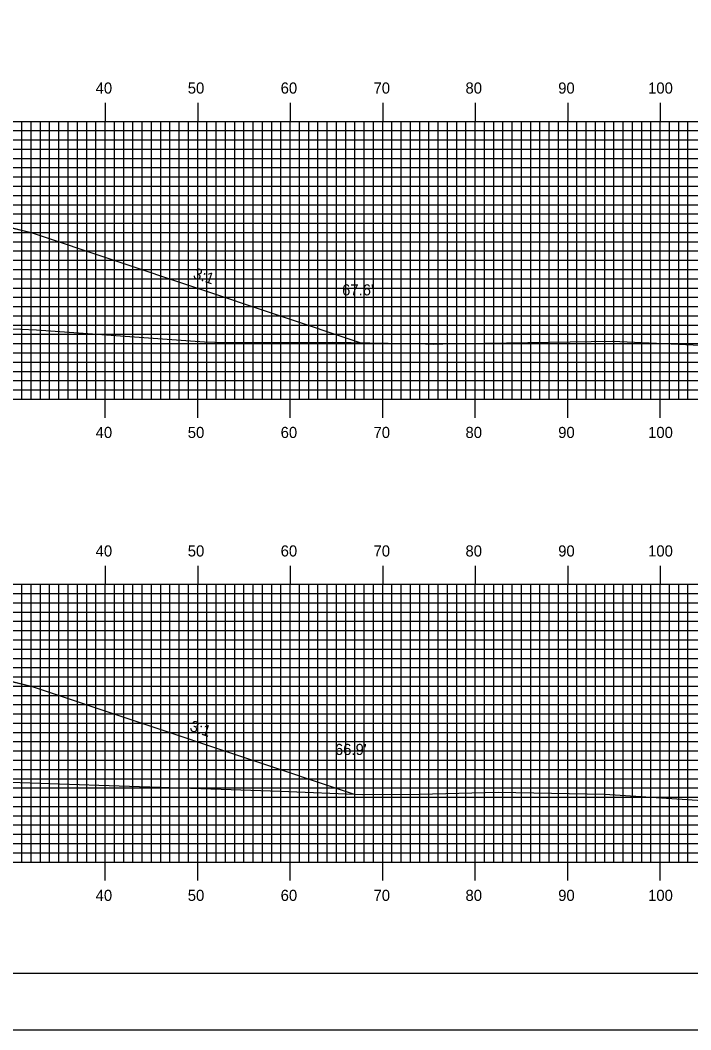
# Model space of a CAD drawing. Extents: x 1806258 to 1806601, y 442591 to 442811.
# Drawn here: x 1806454.5 to 1806527, y 442590.5 to 442699.6 of the extents above; entities that cross this region are included whole.
import ezdxf

# ---------------------------------------------------------------- set-up
doc = ezdxf.new("R2010")
doc.units = 0
for name, color, linetype in [('ANNOTATION', 7, 'Continuous'), ('BORDER', 7, 'Continuous'), ('D_Roadway_Centerline', 7, 'Continuous'), ('D_Roadway_SlopeLines', 7, 'Continuous'), ('D_Text_Standard', 7, 'Continuous'), ('H_V ANNOTATION', 7, 'Continuous'), ('MAJOR', 7, 'Continuous'), ('MINOR', 7, 'Continuous'), ('PLOT BOUNDARY', 7, 'Continuous'), ('S_Roadway_Centerline', 7, 'Continuous')]:
    doc.layers.add(name, color=color, linetype=linetype)

msp = doc.modelspace()

# ---------------------------------------------------------------- linework, layer by layer
at = {"layer": 'BORDER'}
msp.add_lwpolyline([(1806274.13, 442596.67), (1806594.13, 442596.67), (1806594.13, 442806.67), (1806274.13, 442806.67)], close=True, dxfattribs=at)
at = {"layer": 'D_Roadway_Centerline'}
for points in [[(1806368.74, 442668.98), (1806391.73, 442676.65), (1806393.56, 442677.1), (1806403.73, 442679.65), (1806411.73, 442679.97), (1806423.73, 442680.21), (1806435.73, 442679.97), (1806443.73, 442679.65), (1806453.91, 442677.1), (1806455.73, 442676.65), (1806491.38, 442664.76)], [(1806370.93, 442620.71), (1806391.73, 442627.65), (1806393.56, 442628.1), (1806403.73, 442630.65), (1806411.73, 442630.97), (1806423.73, 442631.21), (1806435.73, 442630.97), (1806443.73, 442630.65), (1806453.91, 442628.1), (1806455.73, 442627.65), (1806490.64, 442616.01)]]:
    msp.add_lwpolyline(points, dxfattribs=at)
at = {"layer": 'D_Roadway_SlopeLines'}
for points in [[(1806443.73, 442679.65), (1806455.73, 442676.65), (1806491.38, 442664.76)], [(1806443.73, 442630.65), (1806455.73, 442627.65), (1806490.64, 442616.01)]]:
    msp.add_lwpolyline(points, dxfattribs=at)
at = {"layer": 'MAJOR'}
for p, q in [((1806463.73, 442690.67), (1806463.73, 442688.67)), ((1806473.73, 442690.67), (1806473.73, 442688.67)), ((1806483.73, 442690.67), (1806483.73, 442688.67)), ((1806493.73, 442690.67), (1806493.73, 442688.67)), ((1806503.73, 442690.67), (1806503.73, 442688.67)), ((1806513.73, 442690.67), (1806513.73, 442688.67)), ((1806523.73, 442690.67), (1806523.73, 442688.67)), ((1806283.73, 442688.67), (1806563.73, 442688.67)), ((1806283.73, 442688.67), (1806563.73, 442688.67)), ((1806463.73, 442658.67), (1806463.73, 442688.67)), ((1806473.73, 442658.67), (1806473.73, 442688.67)), ((1806483.73, 442658.67), (1806483.73, 442688.67)), ((1806493.73, 442658.67), (1806493.73, 442688.67)), ((1806503.73, 442658.67), (1806503.73, 442688.67)), ((1806513.73, 442658.67), (1806513.73, 442688.67)), ((1806523.73, 442658.67), (1806523.73, 442688.67)), ((1806283.73, 442683.67), (1806563.73, 442683.67)), ((1806283.73, 442678.67), (1806563.73, 442678.67)), ((1806283.73, 442673.67), (1806563.73, 442673.67)), ((1806283.73, 442668.67), (1806563.73, 442668.67)), ((1806283.73, 442663.67), (1806563.73, 442663.67)), ((1806283.73, 442658.67), (1806563.73, 442658.67)), ((1806283.73, 442658.67), (1806563.73, 442658.67)), ((1806463.73, 442656.66), (1806463.73, 442658.67)), ((1806473.73, 442656.66), (1806473.73, 442658.67)), ((1806483.73, 442656.66), (1806483.73, 442658.67)), ((1806493.73, 442656.66), (1806493.73, 442658.67)), ((1806503.73, 442656.66), (1806503.73, 442658.67)), ((1806513.73, 442656.66), (1806513.73, 442658.67)), ((1806523.73, 442656.66), (1806523.73, 442658.67)), ((1806463.73, 442640.67), (1806463.73, 442638.67)), ((1806473.73, 442640.67), (1806473.73, 442638.67)), ((1806483.73, 442640.67), (1806483.73, 442638.67)), ((1806493.73, 442640.67), (1806493.73, 442638.67)), ((1806503.73, 442640.67), (1806503.73, 442638.67)), ((1806513.73, 442640.67), (1806513.73, 442638.67)), ((1806523.73, 442640.67), (1806523.73, 442638.67)), ((1806283.73, 442638.67), (1806563.73, 442638.67)), ((1806283.73, 442638.67), (1806563.73, 442638.67)), ((1806463.73, 442608.67), (1806463.73, 442638.67)), ((1806473.73, 442608.67), (1806473.73, 442638.67)), ((1806483.73, 442608.67), (1806483.73, 442638.67)), ((1806493.73, 442608.67), (1806493.73, 442638.67)), ((1806503.73, 442608.67), (1806503.73, 442638.67)), ((1806513.73, 442608.67), (1806513.73, 442638.67)), ((1806523.73, 442608.67), (1806523.73, 442638.67)), ((1806283.73, 442633.67), (1806563.73, 442633.67)), ((1806283.73, 442628.67), (1806563.73, 442628.67)), ((1806283.73, 442623.67), (1806563.73, 442623.67)), ((1806283.73, 442618.67), (1806563.73, 442618.67)), ((1806283.73, 442613.67), (1806563.73, 442613.67)), ((1806283.73, 442608.67), (1806563.73, 442608.67)), ((1806283.73, 442608.67), (1806563.73, 442608.67)), ((1806463.73, 442606.66), (1806463.73, 442608.67)), ((1806473.73, 442606.66), (1806473.73, 442608.67)), ((1806483.73, 442606.66), (1806483.73, 442608.67)), ((1806493.73, 442606.66), (1806493.73, 442608.67)), ((1806503.73, 442606.66), (1806503.73, 442608.67)), ((1806513.73, 442606.66), (1806513.73, 442608.67)), ((1806523.73, 442606.66), (1806523.73, 442608.67))]:
    msp.add_line(p, q, dxfattribs=at)
at = {"layer": 'MINOR'}
for p, q in [((1806454.73, 442658.67), (1806454.73, 442688.67)), ((1806455.73, 442658.67), (1806455.73, 442688.67)), ((1806456.73, 442658.67), (1806456.73, 442688.67)), ((1806457.73, 442658.67), (1806457.73, 442688.67)), ((1806458.73, 442658.67), (1806458.73, 442688.67)), ((1806459.73, 442658.67), (1806459.73, 442688.67)), ((1806460.73, 442658.67), (1806460.73, 442688.67)), ((1806461.73, 442658.67), (1806461.73, 442688.67)), ((1806462.73, 442658.67), (1806462.73, 442688.67)), ((1806464.73, 442658.67), (1806464.73, 442688.67)), ((1806465.73, 442658.67), (1806465.73, 442688.67)), ((1806466.73, 442658.67), (1806466.73, 442688.67)), ((1806467.73, 442658.67), (1806467.73, 442688.67)), ((1806468.73, 442658.67), (1806468.73, 442688.67)), ((1806469.73, 442658.67), (1806469.73, 442688.67)), ((1806470.73, 442658.67), (1806470.73, 442688.67)), ((1806471.73, 442658.67), (1806471.73, 442688.67)), ((1806472.73, 442658.67), (1806472.73, 442688.67)), ((1806474.73, 442658.67), (1806474.73, 442688.67)), ((1806475.73, 442658.67), (1806475.73, 442688.67)), ((1806476.73, 442658.67), (1806476.73, 442688.67)), ((1806477.73, 442658.67), (1806477.73, 442688.67)), ((1806478.73, 442658.67), (1806478.73, 442688.67)), ((1806479.73, 442658.67), (1806479.73, 442688.67)), ((1806480.73, 442658.67), (1806480.73, 442688.67)), ((1806481.73, 442658.67), (1806481.73, 442688.67)), ((1806482.73, 442658.67), (1806482.73, 442688.67)), ((1806484.73, 442658.67), (1806484.73, 442688.67)), ((1806485.73, 442658.67), (1806485.73, 442688.67)), ((1806486.73, 442658.67), (1806486.73, 442688.67)), ((1806487.73, 442658.67), (1806487.73, 442688.67)), ((1806488.73, 442658.67), (1806488.73, 442688.67)), ((1806489.73, 442658.67), (1806489.73, 442688.67)), ((1806490.73, 442658.67), (1806490.73, 442688.67)), ((1806491.73, 442658.67), (1806491.73, 442688.67)), ((1806492.73, 442658.67), (1806492.73, 442688.67)), ((1806494.73, 442658.67), (1806494.73, 442688.67)), ((1806495.73, 442658.67), (1806495.73, 442688.67)), ((1806496.73, 442658.67), (1806496.73, 442688.67)), ((1806497.73, 442658.67), (1806497.73, 442688.67)), ((1806498.73, 442658.67), (1806498.73, 442688.67)), ((1806499.73, 442658.67), (1806499.73, 442688.67)), ((1806500.73, 442658.67), (1806500.73, 442688.67)), ((1806501.73, 442658.67), (1806501.73, 442688.67)), ((1806502.73, 442658.67), (1806502.73, 442688.67)), ((1806504.73, 442658.67), (1806504.73, 442688.67)), ((1806505.73, 442658.67), (1806505.73, 442688.67)), ((1806506.73, 442658.67), (1806506.73, 442688.67)), ((1806507.73, 442658.67), (1806507.73, 442688.67)), ((1806508.73, 442658.67), (1806508.73, 442688.67)), ((1806509.73, 442658.67), (1806509.73, 442688.67)), ((1806510.73, 442658.67), (1806510.73, 442688.67)), ((1806511.73, 442658.67), (1806511.73, 442688.67)), ((1806512.73, 442658.67), (1806512.73, 442688.67)), ((1806514.73, 442658.67), (1806514.73, 442688.67)), ((1806515.73, 442658.67), (1806515.73, 442688.67)), ((1806516.73, 442658.67), (1806516.73, 442688.67)), ((1806517.73, 442658.67), (1806517.73, 442688.67)), ((1806518.73, 442658.67), (1806518.73, 442688.67)), ((1806519.73, 442658.67), (1806519.73, 442688.67)), ((1806520.73, 442658.67), (1806520.73, 442688.67)), ((1806521.73, 442658.67), (1806521.73, 442688.67)), ((1806522.73, 442658.67), (1806522.73, 442688.67)), ((1806524.73, 442658.67), (1806524.73, 442688.67)), ((1806525.73, 442658.67), (1806525.73, 442688.67)), ((1806526.73, 442658.67), (1806526.73, 442688.67)), ((1806283.73, 442687.67), (1806563.73, 442687.67)), ((1806283.73, 442686.67), (1806563.73, 442686.67)), ((1806283.73, 442685.67), (1806563.73, 442685.67)), ((1806283.73, 442684.67), (1806563.73, 442684.67)), ((1806283.73, 442682.67), (1806563.73, 442682.67)), ((1806283.73, 442681.67), (1806563.73, 442681.67)), ((1806283.73, 442680.67), (1806563.73, 442680.67)), ((1806283.73, 442679.67), (1806563.73, 442679.67)), ((1806283.73, 442677.67), (1806563.73, 442677.67)), ((1806283.73, 442676.67), (1806563.73, 442676.67)), ((1806283.73, 442675.67), (1806563.73, 442675.67)), ((1806283.73, 442674.67), (1806563.73, 442674.67)), ((1806283.73, 442672.67), (1806563.73, 442672.67)), ((1806283.73, 442671.67), (1806563.73, 442671.67)), ((1806283.73, 442670.67), (1806563.73, 442670.67)), ((1806283.73, 442669.67), (1806563.73, 442669.67)), ((1806283.73, 442667.67), (1806563.73, 442667.67)), ((1806283.73, 442666.67), (1806563.73, 442666.67)), ((1806283.73, 442665.67), (1806563.73, 442665.67)), ((1806283.73, 442664.67), (1806563.73, 442664.67)), ((1806283.73, 442662.67), (1806563.73, 442662.67)), ((1806283.73, 442661.67), (1806563.73, 442661.67)), ((1806283.73, 442660.67), (1806563.73, 442660.67)), ((1806283.73, 442659.67), (1806563.73, 442659.67)), ((1806454.73, 442608.67), (1806454.73, 442638.67)), ((1806455.73, 442608.67), (1806455.73, 442638.67)), ((1806456.73, 442608.67), (1806456.73, 442638.67)), ((1806457.73, 442608.67), (1806457.73, 442638.67)), ((1806458.73, 442608.67), (1806458.73, 442638.67)), ((1806459.73, 442608.67), (1806459.73, 442638.67)), ((1806460.73, 442608.67), (1806460.73, 442638.67)), ((1806461.73, 442608.67), (1806461.73, 442638.67)), ((1806462.73, 442608.67), (1806462.73, 442638.67)), ((1806464.73, 442608.67), (1806464.73, 442638.67)), ((1806465.73, 442608.67), (1806465.73, 442638.67)), ((1806466.73, 442608.67), (1806466.73, 442638.67)), ((1806467.73, 442608.67), (1806467.73, 442638.67)), ((1806468.73, 442608.67), (1806468.73, 442638.67)), ((1806469.73, 442608.67), (1806469.73, 442638.67)), ((1806470.73, 442608.67), (1806470.73, 442638.67)), ((1806471.73, 442608.67), (1806471.73, 442638.67)), ((1806472.73, 442608.67), (1806472.73, 442638.67)), ((1806474.73, 442608.67), (1806474.73, 442638.67)), ((1806475.73, 442608.67), (1806475.73, 442638.67)), ((1806476.73, 442608.67), (1806476.73, 442638.67)), ((1806477.73, 442608.67), (1806477.73, 442638.67)), ((1806478.73, 442608.67), (1806478.73, 442638.67)), ((1806479.73, 442608.67), (1806479.73, 442638.67)), ((1806480.73, 442608.67), (1806480.73, 442638.67)), ((1806481.73, 442608.67), (1806481.73, 442638.67)), ((1806482.73, 442608.67), (1806482.73, 442638.67)), ((1806484.73, 442608.67), (1806484.73, 442638.67)), ((1806485.73, 442608.67), (1806485.73, 442638.67)), ((1806486.73, 442608.67), (1806486.73, 442638.67)), ((1806487.73, 442608.67), (1806487.73, 442638.67)), ((1806488.73, 442608.67), (1806488.73, 442638.67)), ((1806489.73, 442608.67), (1806489.73, 442638.67)), ((1806490.73, 442608.67), (1806490.73, 442638.67)), ((1806491.73, 442608.67), (1806491.73, 442638.67)), ((1806492.73, 442608.67), (1806492.73, 442638.67)), ((1806494.73, 442608.67), (1806494.73, 442638.67)), ((1806495.73, 442608.67), (1806495.73, 442638.67)), ((1806496.73, 442608.67), (1806496.73, 442638.67)), ((1806497.73, 442608.67), (1806497.73, 442638.67)), ((1806498.73, 442608.67), (1806498.73, 442638.67)), ((1806499.73, 442608.67), (1806499.73, 442638.67)), ((1806500.73, 442608.67), (1806500.73, 442638.67)), ((1806501.73, 442608.67), (1806501.73, 442638.67)), ((1806502.73, 442608.67), (1806502.73, 442638.67)), ((1806504.73, 442608.67), (1806504.73, 442638.67)), ((1806505.73, 442608.67), (1806505.73, 442638.67)), ((1806506.73, 442608.67), (1806506.73, 442638.67)), ((1806507.73, 442608.67), (1806507.73, 442638.67)), ((1806508.73, 442608.67), (1806508.73, 442638.67)), ((1806509.73, 442608.67), (1806509.73, 442638.67)), ((1806510.73, 442608.67), (1806510.73, 442638.67)), ((1806511.73, 442608.67), (1806511.73, 442638.67)), ((1806512.73, 442608.67), (1806512.73, 442638.67)), ((1806514.73, 442608.67), (1806514.73, 442638.67)), ((1806515.73, 442608.67), (1806515.73, 442638.67)), ((1806516.73, 442608.67), (1806516.73, 442638.67)), ((1806517.73, 442608.67), (1806517.73, 442638.67)), ((1806518.73, 442608.67), (1806518.73, 442638.67)), ((1806519.73, 442608.67), (1806519.73, 442638.67)), ((1806520.73, 442608.67), (1806520.73, 442638.67)), ((1806521.73, 442608.67), (1806521.73, 442638.67)), ((1806522.73, 442608.67), (1806522.73, 442638.67)), ((1806524.73, 442608.67), (1806524.73, 442638.67)), ((1806525.73, 442608.67), (1806525.73, 442638.67)), ((1806526.73, 442608.67), (1806526.73, 442638.67)), ((1806283.73, 442637.67), (1806563.73, 442637.67)), ((1806283.73, 442636.67), (1806563.73, 442636.67)), ((1806283.73, 442635.67), (1806563.73, 442635.67)), ((1806283.73, 442634.67), (1806563.73, 442634.67)), ((1806283.73, 442632.67), (1806563.73, 442632.67)), ((1806283.73, 442631.67), (1806563.73, 442631.67)), ((1806283.73, 442630.67), (1806563.73, 442630.67)), ((1806283.73, 442629.67), (1806563.73, 442629.67)), ((1806283.73, 442627.67), (1806563.73, 442627.67)), ((1806283.73, 442626.67), (1806563.73, 442626.67)), ((1806283.73, 442625.67), (1806563.73, 442625.67)), ((1806283.73, 442624.67), (1806563.73, 442624.67)), ((1806283.73, 442622.67), (1806563.73, 442622.67)), ((1806283.73, 442621.67), (1806563.73, 442621.67)), ((1806283.73, 442620.67), (1806563.73, 442620.67)), ((1806283.73, 442619.67), (1806563.73, 442619.67)), ((1806283.73, 442617.67), (1806563.73, 442617.67)), ((1806283.73, 442616.67), (1806563.73, 442616.67)), ((1806283.73, 442615.67), (1806563.73, 442615.67)), ((1806283.73, 442614.67), (1806563.73, 442614.67)), ((1806283.73, 442612.67), (1806563.73, 442612.67)), ((1806283.73, 442611.67), (1806563.73, 442611.67)), ((1806283.73, 442610.67), (1806563.73, 442610.67)), ((1806283.73, 442609.67), (1806563.73, 442609.67))]:
    msp.add_line(p, q, dxfattribs=at)
at = {"layer": 'PLOT BOUNDARY'}
msp.add_lwpolyline([(1806257.95, 442590.55), (1806597.95, 442590.55), (1806597.95, 442810.55), (1806257.95, 442810.55)], close=True, dxfattribs=at)
at = {"layer": 'S_Roadway_Centerline'}
for points in [[(1806452.93, 442666.31), (1806456.31, 442666.14), (1806474.47, 442664.87), (1806476.7, 442664.8), (1806488.29, 442664.82), (1806498.37, 442664.63), (1806499.2, 442664.61), (1806500.24, 442664.64), (1806518.57, 442664.92), (1806527.28, 442664.52), (1806540.28, 442663.88), (1806546.17, 442663.92), (1806563.73, 442664.26)], [(1806448.11, 442617.46), (1806463.03, 442616.97), (1806476.28, 442616.54), (1806482.67, 442616.34), (1806491.6, 442615.97), (1806497.72, 442616), (1806506.23, 442616.21), (1806517.73, 442616.01), (1806530.55, 442615.18), (1806544.79, 442614.7), (1806560.67, 442614.25), (1806563.73, 442614.28)]]:
    msp.add_lwpolyline(points, dxfattribs=at)

# ---------------------------------------------------------------- texts
at = {"layer": 'ANNOTATION'}
for p in [(1806473.16, 442671.75), (1806472.79, 442622.87)]:
    msp.add_text('3:1', height=1.2, rotation=341.5652, dxfattribs=at).set_placement(p)
at = {"layer": 'D_Text_Standard'}
for s, p in [("67.6'", (1806489.34, 442669.87)), ("66.9'", (1806488.57, 442620.23))]:
    msp.add_text(s, height=1.2, dxfattribs=at).set_placement(p)
at = {"layer": 'H_V ANNOTATION'}
for s, p in [('40', (1806462.7, 442691.67)), ('50', (1806472.66, 442691.67)), ('60', (1806482.7, 442691.67)), ('70', (1806492.74, 442691.67)), ('80', (1806502.68, 442691.67)), ('90', (1806512.7, 442691.67)), ('100', (1806522.42, 442691.67)), ('40', (1806462.7, 442654.47)), ('50', (1806472.66, 442654.47)), ('60', (1806482.7, 442654.47)), ('70', (1806492.74, 442654.47)), ('80', (1806502.68, 442654.47)), ('90', (1806512.7, 442654.47)), ('100', (1806522.42, 442654.47)), ('40', (1806462.7, 442641.67)), ('50', (1806472.66, 442641.67)), ('60', (1806482.7, 442641.67)), ('70', (1806492.74, 442641.67)), ('80', (1806502.68, 442641.67)), ('90', (1806512.7, 442641.67)), ('100', (1806522.42, 442641.67)), ('40', (1806462.7, 442604.47)), ('50', (1806472.66, 442604.47)), ('60', (1806482.7, 442604.47)), ('70', (1806492.74, 442604.47)), ('80', (1806502.68, 442604.47)), ('90', (1806512.7, 442604.47)), ('100', (1806522.42, 442604.47))]:
    msp.add_text(s, height=1.2, dxfattribs=at).set_placement(p)

doc.saveas('drawing.dxf')
